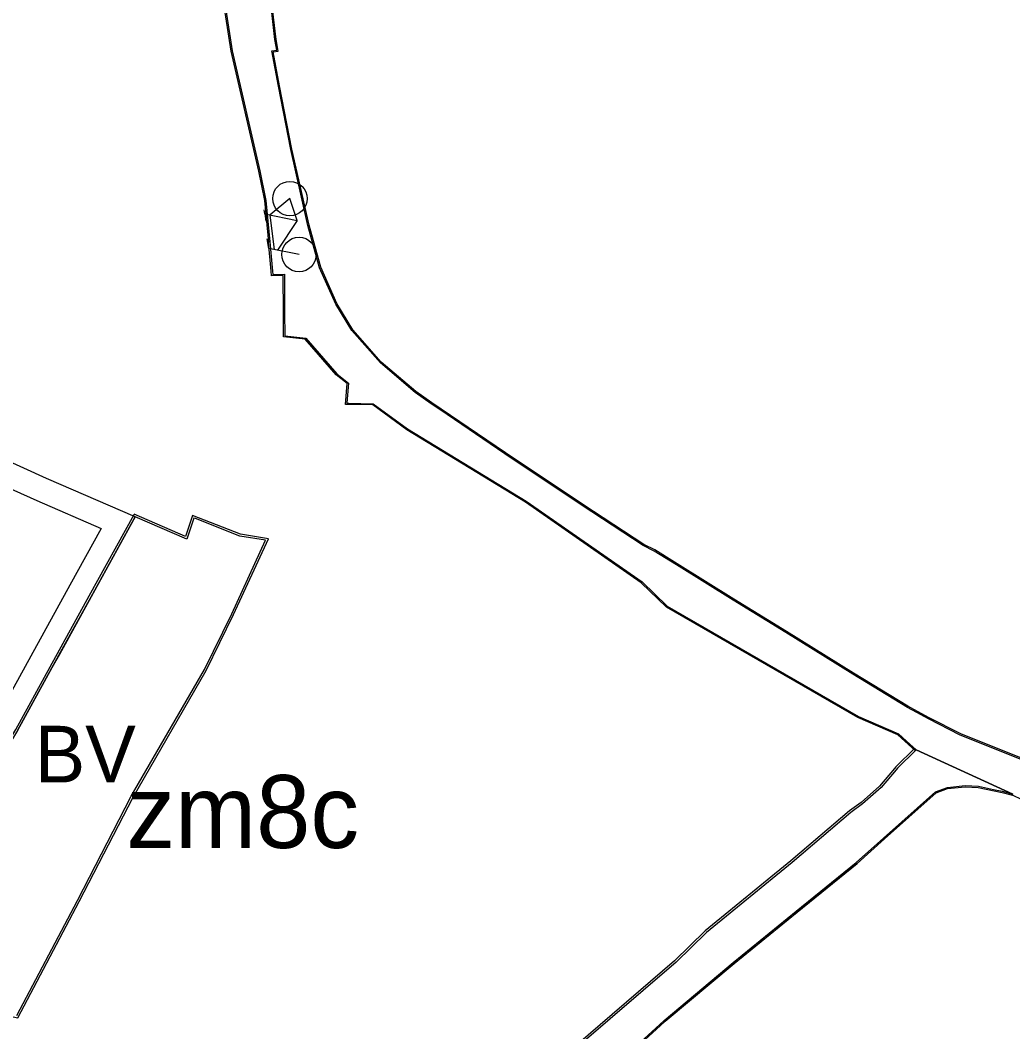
# Model space of a CAD drawing. Extents: x -555070 to -553076, y -1186731 to -1182766.
# Drawn here: x -554659.4 to -554414.1, y -1185288.2 to -1185038.3 of the extents above; entities that cross this region are included whole.
import ezdxf

# ---------------------------------------------------------------- set-up
doc = ezdxf.new("R2010")
doc.units = 0
for name, color, linetype in [('CYKLISTI_stav', 7, 'Continuous'), ('HRANICE_ZMENY_DO_KOO', 7, 'Continuous'), ('Level 10', 7, 'Continuous'), ('Level 13', 7, 'Continuous'), ('Level 52', 7, 'Continuous'), ('Level 59', 7, 'Continuous'), ('OBRYS_PLOCH', 7, 'Continuous'), ('rezerva_BV', 7, 'Continuous'), ('stav_BV', 7, 'Continuous'), ('stav_DS', 7, 'Continuous'), ('ZU_plocha_aktualizace', 7, 'Continuous')]:
    doc.layers.add(name, color=color, linetype=linetype)

msp = doc.modelspace()

# ---------------------------------------------------------------- linework, layer by layer
at = {"layer": 'CYKLISTI_stav'}
for p, q in [((-554592.75, -1185082.39), (-554597.62, -1185086.44)), ((-554590.94, -1185087.84), (-554592.75, -1185082.39)), ((-554598.96, -1185086.15), (-554599.09, -1185085.16)), ((-554598.96, -1185086.15), (-554590.94, -1185087.84)), ((-554598.96, -1185086.15), (-554598.7, -1185087.95)), ((-554596.53, -1185095.02), (-554597.62, -1185086.44)), ((-554590.94, -1185087.84), (-554595.83, -1185095.15)), ((-554597.99, -1185094.72), (-554598.34, -1185092.3)), ((-554590.5, -1185096.2), (-554597.99, -1185094.72))]:
    msp.add_line(p, q, dxfattribs=at)
for centre in [(-554592.75, -1185082.39), (-554590.5, -1185096.2)]:
    msp.add_circle(centre, 4.25, dxfattribs=at)
at = {"layer": 'HRANICE_ZMENY_DO_KOO'}
for p, q in [((-554596.17, -1185043.07), (-554604.28, -1184972.41)), ((-554612.94, -1185009.71), (-554607.32, -1185045.94)), ((-554595.63, -1185045.94), (-554596.17, -1185043.07)), ((-554607.32, -1185045.94), (-554600.5, -1185075.58)), ((-554596.85, -1185046.17), (-554595.63, -1185045.94)), ((-554595.3, -1185054.54), (-554596.85, -1185046.17)), ((-554592.25, -1185070.22), (-554595.3, -1185054.54)), ((-554588.03, -1185088.95), (-554592.25, -1185070.22)), ((-554600.5, -1185075.58), (-554599, -1185082.89)), ((-554599, -1185082.89), (-554598.04, -1185093.14)), ((-554585.13, -1185099.36), (-554588.03, -1185088.95)), ((-554597.37, -1185100.33), (-554598.04, -1185093.14)), ((-554597.26, -1185101.45), (-554597.37, -1185100.33)), ((-554594.42, -1185101.35), (-554597.26, -1185101.45)), ((-554594.37, -1185110.52), (-554594.42, -1185101.35)), ((-554581.15, -1185108.33), (-554585.13, -1185099.36)), ((-554577.2, -1185114.79), (-554581.15, -1185108.33)), ((-554594.33, -1185116.52), (-554594.37, -1185110.52)), ((-554570.19, -1185122.76), (-554577.2, -1185114.79)), ((-554588.99, -1185117.12), (-554594.33, -1185116.52)), ((-554581.35, -1185125.89), (-554588.99, -1185117.12)), ((-554561.63, -1185130.04), (-554570.19, -1185122.76)), ((-554578.58, -1185128.07), (-554581.35, -1185125.89)), ((-554579.05, -1185133.26), (-554578.58, -1185128.07)), ((-554557.65, -1185132.83), (-554561.63, -1185130.04)), ((-554578.19, -1185133.26), (-554579.05, -1185133.26)), ((-554572.26, -1185133.37), (-554578.19, -1185133.26)), ((-554563.88, -1185139.51), (-554572.26, -1185133.37)), ((-554539.46, -1185145.21), (-554557.65, -1185132.83)), ((-554534.52, -1185157.35), (-554563.88, -1185139.51)), ((-554520.34, -1185157.91), (-554539.46, -1185145.21)), ((-554505.94, -1185177.26), (-554534.52, -1185157.35)), ((-554505.29, -1185167.81), (-554520.34, -1185157.91)), ((-554502.62, -1185169.18), (-554505.29, -1185167.81)), ((-554497.06, -1185172.61), (-554502.62, -1185169.18)), ((-554483.1, -1185181.31), (-554497.06, -1185172.61)), ((-554499.71, -1185183.3), (-554505.94, -1185177.26)), ((-554470.08, -1185189.28), (-554483.1, -1185181.31)), ((-554452.43, -1185210.55), (-554499.71, -1185183.3)), ((-554453.52, -1185199.62), (-554470.08, -1185189.28)), ((-554440.04, -1185207.79), (-554453.52, -1185199.62)), ((-554437.72, -1185209.05), (-554440.04, -1185207.79)), ((-554442.52, -1185214.83), (-554452.43, -1185210.55)), ((-554434.82, -1185210.61), (-554437.72, -1185209.05)), ((-554427, -1185214.63), (-554434.82, -1185210.61)), ((-554438.16, -1185218.78), (-554442.52, -1185214.83)), ((-554409.52, -1185221.62), (-554427, -1185214.63)), ((-554438.37, -1185218.15), (-554443.03, -1185222.76)), ((-554443.37, -1185223.16), (-554447.04, -1185227.49)), ((-554443.03, -1185222.76), (-554443.37, -1185223.16)), ((-554447.04, -1185227.49), (-554451.6, -1185231.52)), ((-554454.46, -1185233.6), (-554469.01, -1185245.96)), ((-554451.6, -1185231.52), (-554454.46, -1185233.6)), ((-554469.01, -1185245.96), (-554490.17, -1185263.25)), ((-554490.17, -1185263.25), (-554497.69, -1185270.65)), ((-554497.69, -1185270.65), (-554522.05, -1185291.6))]:
    msp.add_line(p, q, dxfattribs=at)
for points in [[(-554732.22, -1185344.93), (-554722.41, -1185327.9), (-554715.62, -1185316.12), (-554711.52, -1185309), (-554709.27, -1185304.1), (-554703.67, -1185291.93), (-554695.45, -1185274.02), (-554692.41, -1185267.29), (-554688.86, -1185259.43), (-554682.86, -1185249.71), (-554661.74, -1185215.55), (-554660.47, -1185213.5), (-554651.98, -1185198.08), (-554642.32, -1185180.53), (-554631.22, -1185160.38)], [(-554695.16, -1185274.7), (-554677.73, -1185280.92), (-554659.99, -1185284.76), (-554644.8, -1185256.02), (-554631.5, -1185230.24), (-554613.43, -1185198.97), (-554606.65, -1185185.13), (-554598.03, -1185166.4), (-554604.99, -1185165.25), (-554616.78, -1185160.64), (-554618.55, -1185165.81), (-554631.19, -1185160.33)], [(-554537.4, -1185310.93), (-554534.73, -1185313.41), (-554532.82, -1185315.19), (-554532.31, -1185315.67), (-554532.05, -1185314.87), (-554529.73, -1185312.74), (-554527.04, -1185310.28), (-554524.01, -1185307.5), (-554520.98, -1185304.73), (-554517.74, -1185301.76), (-554514.76, -1185299.04), (-554501.19, -1185286.63), (-554500.05, -1185285.59), (-554483.01, -1185271.32), (-554467.44, -1185258.63), (-554452.63, -1185246.62), (-554445.86, -1185240.54), (-554433.11, -1185229.16), (-554430.24, -1185228.1), (-554425.89, -1185227.65), (-554422.67, -1185227.83), (-554416.8, -1185229.06), (-554414.23, -1185229.78)], [(-554397.87, -1185235.98), (-554411.82, -1185230.89), (-554414.24, -1185229.78)]]:
    msp.add_lwpolyline(points, dxfattribs=at)
at = {"layer": 'Level 13'}
for p, q in [((-554652.87, -1185151.49), (-554667.86, -1185144.71)), ((-554630.97, -1185160.97), (-554652.87, -1185151.49)), ((-554630.97, -1185160.97), (-554641.88, -1185180.77)), ((-554641.88, -1185180.77), (-554630.97, -1185160.97)), ((-554618.25, -1185166.48), (-554630.97, -1185160.97)), ((-554605.12, -1185165.73), (-554616.11, -1185161.44)), ((-554641.88, -1185180.77), (-554651.54, -1185198.32)), ((-554649.7, -1185194.97), (-554641.88, -1185180.77)), ((-554651.54, -1185198.32), (-554649.7, -1185194.97)), ((-554651.54, -1185198.32), (-554660.04, -1185213.75)), ((-554660.04, -1185213.75), (-554651.54, -1185198.32))]:
    msp.add_line(p, q, dxfattribs=at)
for points in [[(-554616.11, -1185161.44), (-554616.48, -1185161.3), (-554618.25, -1185166.48)], [(-554660.25, -1185284.19), (-554645.24, -1185255.79), (-554631.94, -1185230), (-554613.87, -1185198.73), (-554607.1, -1185184.92), (-554598.76, -1185166.79), (-554605.12, -1185165.73)]]:
    msp.add_lwpolyline(points, dxfattribs=at)
at = {"layer": 'Level 52'}
for points in [[(-554630.97, -1185160.97), (-554641.88, -1185180.77), (-554651.54, -1185198.32)], [(-554651.54, -1185198.32), (-554660.04, -1185213.75), (-554661.31, -1185215.81), (-554671.87, -1185232.89), (-554682.43, -1185249.97), (-554688.42, -1185259.67), (-554691.95, -1185267.5), (-554694.99, -1185274.23)]]:
    msp.add_lwpolyline(points, dxfattribs=at)
at = {"layer": 'OBRYS_PLOCH'}
for p, q in [((-554596.47, -1185043.12), (-554604.58, -1184972.42)), ((-554596.47, -1185043.12), (-554604.58, -1184972.42)), ((-554608.59, -1185035.81), (-554607.03, -1185045.88)), ((-554608.59, -1185035.81), (-554607.03, -1185045.88)), ((-554595.98, -1185045.7), (-554596.47, -1185043.12)), ((-554595.98, -1185045.7), (-554596.47, -1185043.12)), ((-554607.03, -1185045.88), (-554600.21, -1185075.52)), ((-554607.03, -1185045.88), (-554600.21, -1185075.52)), ((-554597.2, -1185045.93), (-554595.98, -1185045.7)), ((-554597.2, -1185045.93), (-554595.98, -1185045.7)), ((-554595.59, -1185054.6), (-554597.2, -1185045.93)), ((-554595.59, -1185054.6), (-554597.2, -1185045.93)), ((-554592.54, -1185070.28), (-554595.59, -1185054.6)), ((-554592.54, -1185070.28), (-554595.59, -1185054.6)), ((-554588.32, -1185089.02), (-554592.54, -1185070.28)), ((-554588.32, -1185089.02), (-554592.54, -1185070.28)), ((-554600.21, -1185075.52), (-554598.7, -1185082.85)), ((-554600.21, -1185075.52), (-554598.7, -1185082.85)), ((-554598.7, -1185082.85), (-554597.74, -1185093.11)), ((-554598.7, -1185082.85), (-554597.74, -1185093.11)), ((-554585.41, -1185099.46), (-554588.32, -1185089.02)), ((-554585.41, -1185099.46), (-554588.32, -1185089.02)), ((-554597.74, -1185093.11), (-554597.07, -1185100.3)), ((-554597.74, -1185093.11), (-554597.07, -1185100.3)), ((-554597.07, -1185100.3), (-554596.99, -1185101.14)), ((-554597.07, -1185100.3), (-554596.99, -1185101.14)), ((-554596.99, -1185101.14), (-554594.12, -1185101.04)), ((-554596.99, -1185101.14), (-554594.12, -1185101.04)), ((-554594.12, -1185101.04), (-554594.07, -1185110.52)), ((-554594.12, -1185101.04), (-554594.07, -1185110.52)), ((-554581.42, -1185108.47), (-554585.41, -1185099.46)), ((-554581.42, -1185108.47), (-554585.41, -1185099.46)), ((-554577.44, -1185114.97), (-554581.42, -1185108.47)), ((-554577.44, -1185114.97), (-554581.42, -1185108.47)), ((-554594.07, -1185110.52), (-554594.03, -1185116.25)), ((-554594.07, -1185110.52), (-554594.03, -1185116.25)), ((-554594.03, -1185116.25), (-554588.84, -1185116.84)), ((-554594.03, -1185116.25), (-554588.84, -1185116.84)), ((-554570.4, -1185122.97), (-554577.44, -1185114.97)), ((-554570.4, -1185122.97), (-554577.44, -1185114.97)), ((-554588.84, -1185116.84), (-554581.14, -1185125.67)), ((-554588.84, -1185116.84), (-554581.14, -1185125.67)), ((-554561.81, -1185130.28), (-554570.4, -1185122.97)), ((-554561.81, -1185130.28), (-554570.4, -1185122.97)), ((-554581.14, -1185125.67), (-554578.27, -1185127.94)), ((-554581.14, -1185125.67), (-554578.27, -1185127.94)), ((-554578.27, -1185127.94), (-554578.72, -1185132.96)), ((-554578.27, -1185127.94), (-554578.72, -1185132.96)), ((-554557.82, -1185133.08), (-554561.81, -1185130.28)), ((-554557.82, -1185133.08), (-554561.81, -1185130.28)), ((-554578.72, -1185132.96), (-554578.19, -1185132.96)), ((-554578.72, -1185132.96), (-554578.19, -1185132.96)), ((-554555.72, -1185134.51), (-554557.82, -1185133.08)), ((-554555.72, -1185134.51), (-554557.82, -1185133.08)), ((-554539.63, -1185145.46), (-554555.72, -1185134.51)), ((-554539.63, -1185145.46), (-554555.72, -1185134.51)), ((-554563.71, -1185139.26), (-554534.36, -1185157.1)), ((-554563.71, -1185139.26), (-554534.36, -1185157.1)), ((-554520.51, -1185158.16), (-554539.63, -1185145.46)), ((-554520.51, -1185158.16), (-554539.63, -1185145.46)), ((-554534.36, -1185157.1), (-554505.75, -1185177.03)), ((-554534.36, -1185157.1), (-554505.75, -1185177.03)), ((-554505.44, -1185168.07), (-554520.51, -1185158.16)), ((-554505.44, -1185168.07), (-554520.51, -1185158.16)), ((-554630.97, -1185160.97), (-554641.88, -1185180.77)), ((-554618.25, -1185166.48), (-554630.97, -1185160.97)), ((-554605.12, -1185165.73), (-554616.11, -1185161.44)), ((-554502.77, -1185169.44), (-554505.44, -1185168.07)), ((-554502.77, -1185169.44), (-554505.44, -1185168.07)), ((-554497.22, -1185172.86), (-554502.77, -1185169.44)), ((-554497.22, -1185172.86), (-554502.77, -1185169.44)), ((-554483.26, -1185181.57), (-554497.22, -1185172.86)), ((-554483.26, -1185181.57), (-554497.22, -1185172.86)), ((-554505.75, -1185177.03), (-554499.53, -1185183.06)), ((-554505.75, -1185177.03), (-554499.53, -1185183.06)), ((-554641.88, -1185180.77), (-554651.54, -1185198.32)), ((-554499.53, -1185183.06), (-554452.3, -1185210.28)), ((-554499.53, -1185183.06), (-554452.3, -1185210.28)), ((-554470.24, -1185189.54), (-554483.26, -1185181.57)), ((-554470.24, -1185189.54), (-554483.26, -1185181.57)), ((-554453.68, -1185199.88), (-554470.24, -1185189.54)), ((-554453.68, -1185199.88), (-554470.24, -1185189.54)), ((-554651.54, -1185198.32), (-554660.04, -1185213.75)), ((-554440.19, -1185208.05), (-554453.68, -1185199.88)), ((-554440.19, -1185208.05), (-554453.68, -1185199.88)), ((-554437.86, -1185209.31), (-554440.19, -1185208.05)), ((-554437.86, -1185209.31), (-554440.19, -1185208.05)), ((-554452.3, -1185210.28), (-554442.36, -1185214.57)), ((-554452.3, -1185210.28), (-554442.36, -1185214.57)), ((-554435.9, -1185210.37), (-554437.86, -1185209.31)), ((-554435.9, -1185210.37), (-554437.86, -1185209.31)), ((-554434.96, -1185210.88), (-554435.9, -1185210.37)), ((-554434.96, -1185210.88), (-554435.9, -1185210.37)), ((-554427.12, -1185214.9), (-554434.96, -1185210.88)), ((-554427.12, -1185214.9), (-554434.96, -1185210.88)), ((-554442.36, -1185214.57), (-554440.38, -1185216.37)), ((-554442.36, -1185214.57), (-554440.38, -1185216.37)), ((-554409.63, -1185221.9), (-554427.12, -1185214.9)), ((-554409.63, -1185221.9), (-554427.12, -1185214.9)), ((-554440.38, -1185216.37), (-554438.02, -1185218.51)), ((-554440.38, -1185216.37), (-554438.02, -1185218.51)), ((-554438.02, -1185218.51), (-554438.02, -1185218.51)), ((-554442.98, -1185223.48), (-554446.68, -1185227.84)), ((-554433.27, -1185228.9), (-554430.31, -1185227.81))]:
    msp.add_line(p, q, dxfattribs=at)
for points in [[(-554578.19, -1185132.96), (-554572.16, -1185133.07), (-554563.71, -1185139.26)], [(-554578.19, -1185132.96), (-554572.16, -1185133.07), (-554563.71, -1185139.26)], [(-554616.11, -1185161.44), (-554616.48, -1185161.3), (-554618.25, -1185166.48)], [(-554660.25, -1185284.19), (-554645.24, -1185255.79), (-554631.94, -1185230), (-554613.87, -1185198.73), (-554607.1, -1185184.92), (-554598.76, -1185166.79), (-554605.12, -1185165.73)], [(-554438.02, -1185218.51), (-554442.66, -1185223.1), (-554442.98, -1185223.48)], [(-554446.68, -1185227.84), (-554451.29, -1185231.91), (-554454.15, -1185233.99), (-554468.69, -1185246.34)], [(-554430.31, -1185227.81), (-554425.9, -1185227.35), (-554422.63, -1185227.53)], [(-554422.63, -1185227.53), (-554418.91, -1185228.31), (-554416.73, -1185228.77), (-554414.15, -1185229.49)], [(-554483.2, -1185271.09), (-554467.63, -1185258.4), (-554452.82, -1185246.39), (-554446.06, -1185240.32), (-554433.27, -1185228.9)], [(-554468.69, -1185246.34), (-554489.84, -1185263.62), (-554497.35, -1185271.02), (-554521.74, -1185291.99)], [(-554532.45, -1185315.13), (-554532.31, -1185314.7), (-554529.93, -1185312.52), (-554527.24, -1185310.06), (-554524.21, -1185307.28), (-554521.18, -1185304.51), (-554517.94, -1185301.54), (-554514.96, -1185298.82), (-554501.39, -1185286.41), (-554500.25, -1185285.36), (-554483.2, -1185271.09)]]:
    msp.add_lwpolyline(points, dxfattribs=at)
at = {"layer": 'rezerva_BV'}
for p, q in [((-554652.87, -1185151.49), (-554667.86, -1185144.71)), ((-554652.87, -1185151.49), (-554667.86, -1185144.71)), ((-554670.3, -1185150.19), (-554655.3, -1185156.98)), ((-554630.97, -1185160.97), (-554652.87, -1185151.49)), ((-554630.97, -1185160.97), (-554652.87, -1185151.49)), ((-554641.88, -1185180.77), (-554630.97, -1185160.97)), ((-554641.88, -1185180.77), (-554630.97, -1185160.97)), ((-554651.54, -1185198.32), (-554641.88, -1185180.77)), ((-554651.54, -1185198.32), (-554641.88, -1185180.77)), ((-554660.04, -1185213.75), (-554651.54, -1185198.32)), ((-554660.04, -1185213.75), (-554651.54, -1185198.32))]:
    msp.add_line(p, q, dxfattribs=at)
msp.add_lwpolyline([(-554655.3, -1185156.98), (-554639.41, -1185163.85), (-554647.14, -1185177.88), (-554656.8, -1185195.43), (-554665.22, -1185210.73), (-554666.42, -1185212.66), (-554687.53, -1185246.82)], dxfattribs=at)
at = {"layer": 'stav_BV'}
for p, q in [((-554630.97, -1185160.97), (-554641.88, -1185180.77)), ((-554618.25, -1185166.48), (-554630.97, -1185160.97)), ((-554605.12, -1185165.73), (-554616.11, -1185161.44)), ((-554641.88, -1185180.77), (-554651.54, -1185198.32)), ((-554651.54, -1185198.32), (-554660.04, -1185213.75))]:
    msp.add_line(p, q, dxfattribs=at)
for points in [[(-554616.11, -1185161.44), (-554616.48, -1185161.3), (-554618.25, -1185166.48)], [(-554660.25, -1185284.19), (-554645.24, -1185255.79), (-554631.94, -1185230), (-554613.87, -1185198.73), (-554607.1, -1185184.92), (-554598.76, -1185166.79), (-554605.12, -1185165.73)]]:
    msp.add_lwpolyline(points, dxfattribs=at)
at = {"layer": 'stav_DS'}
for p, q in [((-554596.47, -1185043.12), (-554604.58, -1184972.42)), ((-554608.59, -1185035.81), (-554607.03, -1185045.88)), ((-554595.98, -1185045.7), (-554596.47, -1185043.12)), ((-554607.03, -1185045.88), (-554600.21, -1185075.52)), ((-554597.2, -1185045.93), (-554595.98, -1185045.7)), ((-554595.59, -1185054.6), (-554597.2, -1185045.93)), ((-554592.54, -1185070.28), (-554595.59, -1185054.6)), ((-554588.32, -1185089.02), (-554592.54, -1185070.28)), ((-554600.21, -1185075.52), (-554598.7, -1185082.85)), ((-554598.7, -1185082.85), (-554597.74, -1185093.11)), ((-554585.41, -1185099.46), (-554588.32, -1185089.02)), ((-554597.74, -1185093.11), (-554597.07, -1185100.3)), ((-554597.07, -1185100.3), (-554596.99, -1185101.14)), ((-554596.99, -1185101.14), (-554594.12, -1185101.04)), ((-554594.12, -1185101.04), (-554594.07, -1185110.52)), ((-554581.42, -1185108.47), (-554585.41, -1185099.46)), ((-554577.44, -1185114.97), (-554581.42, -1185108.47)), ((-554594.07, -1185110.52), (-554594.03, -1185116.25)), ((-554594.03, -1185116.25), (-554588.84, -1185116.84)), ((-554570.4, -1185122.97), (-554577.44, -1185114.97)), ((-554588.84, -1185116.84), (-554581.14, -1185125.67)), ((-554561.81, -1185130.28), (-554570.4, -1185122.97)), ((-554581.14, -1185125.67), (-554578.27, -1185127.94)), ((-554578.27, -1185127.94), (-554578.72, -1185132.96)), ((-554557.82, -1185133.08), (-554561.81, -1185130.28)), ((-554578.72, -1185132.96), (-554578.19, -1185132.96)), ((-554555.72, -1185134.51), (-554557.82, -1185133.08)), ((-554539.63, -1185145.46), (-554555.72, -1185134.51)), ((-554563.71, -1185139.26), (-554534.36, -1185157.1)), ((-554520.51, -1185158.16), (-554539.63, -1185145.46)), ((-554534.36, -1185157.1), (-554505.75, -1185177.03)), ((-554505.44, -1185168.07), (-554520.51, -1185158.16)), ((-554502.77, -1185169.44), (-554505.44, -1185168.07)), ((-554497.22, -1185172.86), (-554502.77, -1185169.44)), ((-554483.26, -1185181.57), (-554497.22, -1185172.86)), ((-554505.75, -1185177.03), (-554499.53, -1185183.06)), ((-554499.53, -1185183.06), (-554452.3, -1185210.28)), ((-554470.24, -1185189.54), (-554483.26, -1185181.57)), ((-554453.68, -1185199.88), (-554470.24, -1185189.54)), ((-554440.19, -1185208.05), (-554453.68, -1185199.88)), ((-554437.86, -1185209.31), (-554440.19, -1185208.05)), ((-554452.3, -1185210.28), (-554442.36, -1185214.57)), ((-554435.9, -1185210.37), (-554437.86, -1185209.31)), ((-554434.96, -1185210.88), (-554435.9, -1185210.37)), ((-554427.12, -1185214.9), (-554434.96, -1185210.88)), ((-554442.36, -1185214.57), (-554440.38, -1185216.37)), ((-554409.63, -1185221.9), (-554427.12, -1185214.9)), ((-554440.38, -1185216.37), (-554438.02, -1185218.51)), ((-554438.02, -1185218.51), (-554414.14, -1185229.49)), ((-554414.15, -1185229.49), (-554438.02, -1185218.51)), ((-554442.98, -1185223.48), (-554446.68, -1185227.84)), ((-554416.73, -1185228.77), (-554414.15, -1185229.49))]:
    msp.add_line(p, q, dxfattribs=at)
for points in [[(-554578.19, -1185132.96), (-554572.16, -1185133.07), (-554563.71, -1185139.26)], [(-554438.02, -1185218.51), (-554442.66, -1185223.1), (-554442.98, -1185223.48)], [(-554446.68, -1185227.84), (-554451.29, -1185231.91), (-554454.15, -1185233.99), (-554468.69, -1185246.34)], [(-554433.27, -1185228.9), (-554430.31, -1185227.81), (-554425.9, -1185227.35), (-554422.63, -1185227.53), (-554418.91, -1185228.31), (-554416.73, -1185228.77), (-554414.14, -1185229.49)], [(-554433.27, -1185228.9), (-554430.31, -1185227.81), (-554425.9, -1185227.35), (-554422.63, -1185227.53), (-554418.91, -1185228.31), (-554416.73, -1185228.77)], [(-554483.2, -1185271.09), (-554467.63, -1185258.4), (-554452.82, -1185246.39), (-554446.06, -1185240.32), (-554433.27, -1185228.9)], [(-554468.69, -1185246.34), (-554489.84, -1185263.62), (-554497.35, -1185271.02), (-554521.74, -1185291.99)], [(-554532.45, -1185315.13), (-554532.31, -1185314.7), (-554529.93, -1185312.52), (-554527.24, -1185310.06), (-554524.21, -1185307.28), (-554521.18, -1185304.51), (-554517.94, -1185301.54), (-554514.96, -1185298.82), (-554501.39, -1185286.41), (-554500.25, -1185285.36), (-554483.2, -1185271.09)]]:
    msp.add_lwpolyline(points, dxfattribs=at)
at = {"layer": 'ZU_plocha_aktualizace'}
for p, q in [((-554630.97, -1185160.97), (-554641.88, -1185180.77)), ((-554618.25, -1185166.48), (-554630.97, -1185160.97)), ((-554605.12, -1185165.73), (-554616.11, -1185161.44)), ((-554641.88, -1185180.77), (-554649.7, -1185194.97)), ((-554649.7, -1185194.97), (-554651.54, -1185198.32)), ((-554651.54, -1185198.32), (-554660.04, -1185213.75))]:
    msp.add_line(p, q, dxfattribs=at)
for points in [[(-554616.11, -1185161.44), (-554616.48, -1185161.3), (-554618.25, -1185166.48)], [(-554660.25, -1185284.19), (-554645.24, -1185255.79), (-554631.94, -1185230), (-554613.87, -1185198.73), (-554607.1, -1185184.92), (-554598.76, -1185166.79), (-554605.12, -1185165.73)]]:
    msp.add_lwpolyline(points, dxfattribs=at)

# ---------------------------------------------------------------- texts
at = {"layer": 'Level 10'}
msp.add_text('zm8c', height=18, dxfattribs=at).set_placement((-554633.17, -1185242.78))
at = {"layer": 'Level 59'}
msp.add_text('BV', height=14, dxfattribs=at).set_placement((-554655.81, -1185226.61))

doc.saveas('drawing.dxf')
